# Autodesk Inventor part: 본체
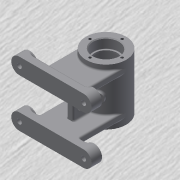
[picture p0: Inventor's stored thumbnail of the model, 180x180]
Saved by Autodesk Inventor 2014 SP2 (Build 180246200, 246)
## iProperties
Created: 2015-11
Part Number: 본체
Material: Generic
Document SubType Name: Modeling
Designer: 702
Density: 1 g/cm^3
Appearance: Default
Author: 702
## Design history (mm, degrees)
sketch "스케치1"
  geometry: C1 r 25 at (0, 0); 1 further point
  constraints: 1 centre point, 1 coincident
  dimensions: "d0" = 50 diameter of C1
extrude "돌출1" new body sketch "스케치1" stored distance "d1" = 70; taper "d2" = 0 deg
node "작업 평면1"
sketch "스케치2"
  geometry: L1 (-25, 0)-(-25, -58); L2 (-25, -58)-(25, -58); L3 (25, -58)-(25, 0); A1 r 25 centre (0, 0) between (-25, 0) and (25, 0) reference; A2 r 25 centre (0, 0) between (-25, 0) and (25, 0); 1 further point
  constraints: 6 end point, 4 point on circle, 2 tangent, 1 centre point, 1 coincident, 1 concentric, 1 perpendicular, 1 vertical
  dimensions: "d4" = 50 distance of L1.end L2.end; "d5" = 58 distance of L1.start L1.end
extrude "돌출2" join sketch "스케치2" distance "d6" = 8; taper "d7" = 0 deg
sketch "스케치3"
  geometry: L1 (0, 0)-(50, 0) reference; L2 (50, 0)-(50, 8) reference; L3 (0, 8)-(50, 8) reference; L4 (0, 0)-(0, 8) reference; L5 (65, 0)-(-15, 0); L6 (-15, 20)-(65, 20); A1 r 10 centre (-15, 10) between (-15, 20) and (-15, 0); A2 r 10 centre (65, 10) between (65, 0) and (65, 20); 2 further points
  constraints: 4 end point, 4 point on circle, 4 tangent, 2 centre point, 2 point on line, 1 midpoint, 1 parallel, 1 vertical alignment
  dimensions: "d8" = 20 distance between parallel lines of L5 L6; "d9" = 80 distance of A2.centre A1.centre
extrude "돌출3" join sketch "스케치3" distance "d10" = 10; taper "d11" = 0 deg
sketch "스케치4"
  geometry: C1 r 10 at (-15, -10); C2 r 10 at (65, -10); A1 r 10 centre (-15, -10) between (-15, 0) and (-15, -20) reference; A2 r 10 centre (65, -10) between (65, -20) and (65, 0) reference; 1 further point
  constraints: 2 centre point, 2 coincident, 1 equal radius
  dimensions: "d12" = 20 diameter of C1
extrude "돌출4" join sketch "스케치4" distance "d13" = 3; taper "d14" = 0 deg
hole "구멍1" diameter "d17" = 6; stored, may be unused: countersink angle "d21" = 90 deg, drill point angle "d23" = 118 deg; dims "d15" = 10, "d16" = 10, "d18" = 6, "d19" = 12, "d20" = 4, "d22" = 8
fillet "모깎기1" dims "d24" = 0.3
chamfer "모따기1" distance "d25" = 1; stored, may be unused: second distance "d26" = 2, angle "d27" = 45 deg
sketch "스케치5"
  geometry: L1 (-25, -35)-(-25, 35) reference; L2 (0, 20)-(-58, 20) reference; L3 (0, -20)-(-58, -20) reference; L4 (-45, 23.977)-(-45, -23.977); L5 (-45, 23.977)-(-20.486, 23.977); L6 (-20.486, 23.977)-(-20.486, -23.977); L7 (-20.486, -23.977)-(-45, -23.977); 2 further points
  constraints: 8 end point, 2 parallel, 2 perpendicular, 1 horizontal alignment, 1 midpoint
  dimensions: "d28" = 20 distance between parallel lines of L1 L4; "d29" = 47.95318 distance of L4.start L4.end; "d30" = 24.51379 distance between parallel lines of L4 L6
extrude "돌출5" join sketch "스케치5" stored distance "d31" = 8; taper "d32" = 0 deg
sketch "스케치6"
  geometry: L1 (-20, -24.678)-(20, -24.678) reference; L2 (-8, -35)-(8, -35); L3 (-8, -38.5)-(8, -38.5); L4 (8, -31.5)-(-8, -31.5); L5 (33, -68)-(27, -68) reference; A1 r 3.5 centre (-8, -35) between (-8, -31.5) and (-8, -38.5); A2 r 3.5 centre (8, -35) between (8, -38.5) and (8, -31.5); 2 further points
  constraints: 8 end point, 4 point on circle, 4 tangent, 2 centre point, 2 parallel, 1 midpoint, 1 vertical alignment
  dimensions: "d33" = 3.5 radius of A2; "d34" = 23 dimension on A1 A2; "d35" = 33 distance from line of L5 L2.end
extrude "돌출6" cut sketch "스케치6" stored distance "d36" = 8; taper "d37" = 0 deg
hole "구멍2" diameter "d40" = 32; stored, may be unused: countersink angle "d44" = 90 deg, drill point angle "d46" = 0 deg; dims "d38" = 10, "d39" = 10, "d41" = 6, "d42" = 12, "d43" = 4, "d45" = 12
hole "구멍3" diameter "d49" = 28; stored, may be unused: countersink angle "d53" = 90 deg, drill point angle "d55" = 0 deg; dims "d47" = 10, "d48" = 10, "d50" = 6, "d51" = 12, "d52" = 4, "d54" = 2
hole "구멍4" diameter "d58" = 42; stored, may be unused: countersink angle "d62" = 90 deg, drill point angle "d64" = 0 deg; dims "d56" = 10, "d57" = 10, "d59" = 6, "d60" = 12, "d61" = 4, "d63" = 42
sketch "스케치7"
  geometry: C1 r 16 at (0, 0) reference; 1 further point
  constraints: 1 vertical alignment
  dimensions: "d65" = 20 distance of C1.centre point (0, 20)
hole "구멍5" sketch "스케치7" at (0, 20) diameter "d66" = 3.242; stored, may be unused: countersink angle "d70" = 90 deg, drill point angle "d72" = 118 deg; dims "d67" = 8, "d68" = 12, "d69" = 4, "d71" = 10
sketch "스케치8"
  geometry: L1 (22.307, 5)-(28, 5); L2 (28, 5)-(28, 0); L3 (28, 0)-(22.307, 0); L4 (22.307, 0)-(22.307, 5); L5 (25, -35)-(25, 35) reference; 1 further point
  constraints: 8 end point, 2 perpendicular, 1 horizontal, 1 horizontal alignment, 1 parallel
  dimensions: "d76" = 5 distance of L1.end L2.end; "d77" = 3 distance between parallel lines of L5 L2; "d78" = 5.69299 distance of L2.end L3.end
revolve "회전1" sketch "스케치8" stored, may be unused: angle "d79" = 90 deg
hole "구멍6" diameter "d82" = 5.188; stored, may be unused: countersink angle "d86" = 90 deg, drill point angle "d88" = 118 deg; dims "d80" = 10, "d81" = 10, "d83" = 8, "d84" = 12, "d85" = 4, "d87" = 10
sketch "스케치9"
  geometry: L1 (0, 0)-(7.164, 0); L2 (0, 0)-(14, -24.249); L3 (14, -24.249)-(19.196, -21.249); L4 (19.196, -21.249)-(16.578, -16.715); L5 (16.578, -16.715)-(11.382, -19.715)
  constraints: 10 end point, 3 perpendicular, 1 horizontal, 1 point on line
  dimensions: "d89" = 60 deg angle of L1 L2; "d90" = 28 distance of L1.start L2.end; "d91" = 6 distance of L2.end L3.end; "d92" = 5.23539 distance of L3.end L4.end
revolve "회전2" sketch "스케치9" stored, may be unused: angle "d93" = 90 deg
hole "구멍7" diameter "d96" = 5.188; stored, may be unused: countersink angle "d100" = 90 deg, drill point angle "d102" = 118 deg; dims "d94" = 10, "d95" = 10, "d97" = 8, "d98" = 12, "d99" = 4, "d101" = 10
node "작업 평면2"
sketch "스케치10"
  geometry: L1 (-25, -35)-(25, -35) reference; L2 (-25, -35)-(-25, 35) reference; 2 further points
  constraints: 1 other
  dimensions: "d103" = 35 distance from line of L1 point (0, 0); "d104" = 25 distance from line of point (0, 0) L2
feature "엠보싱1" sketch "스케치10" dims "d0" = 50, "d105" = 0.5, "d106" = 0
fillet "모깎기2" dims "d107" = 0.3
fillet "모깎기3" dims "d108" = 3
fillet "모깎기4" dims "d109" = 2
fillet "모깎기5" dims "d110" = 2
fillet "모깎기6" dims "d111" = 2
fillet "모깎기7" dims "d112" = 2
chamfer "모따기2" distance "d113" = 1; stored, may be unused: second distance "d114" = 2, angle "d115" = 45 deg
node "솔리드1"
mirror "대칭1"
mirror "대칭2"
mirror "대칭3"
pattern_circular "원형 패턴1" dims angle "d74" = 360 deg
mirror "대칭4"
